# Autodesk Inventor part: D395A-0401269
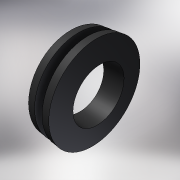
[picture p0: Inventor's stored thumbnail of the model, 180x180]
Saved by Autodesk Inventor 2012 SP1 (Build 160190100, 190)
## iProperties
Shininess: 69.0
Length Units: 11269
Angle Units: 11279
Time Units: 11290
Mass Units: 11283
Length Display Precision: 3
Angle Display Precision: 2
Created: 2002-06
Part Number: D395A-0401269
Material: Rubber
Document SubType Name: Modeling
Designer: LAlexey
Density: 0.93 g/cm^3
Mass: 3.61777 g
Surface Area: 34.5575 cm^2
Volume: 3.89008 cm^3
Density: 1.06
Volumn: 3.8900771033075623
Area: 34.55751918948772
PropertySet Name: Model Information
Control State: 0
Master: False
Checked Out: True
Checked Out Date: 2008-10-15
Last Check In Date: 2008-10-15
Author: LAlexey
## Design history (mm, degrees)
body "Solid1"
revolve "Revolution1" stored, may be unused: angle "d6" = 90 deg
sketch "Sketch1"
  geometry: L1 (0.27, 33.081)-(0.27, 40.581); L2 (0.27, 40.581)-(2.77, 40.581); L3 (2.77, 40.581)-(2.77, 36.081); L4 (2.77, 36.081)-(5.77, 36.081); L5 (5.77, 36.081)-(5.77, 40.581); L6 (5.77, 40.581)-(8.27, 40.581); L7 (8.27, 40.581)-(8.27, 33.081); L8 (8.27, 33.081)-(0.27, 33.081); L9 (6.357, 23.081)-(8.857, 23.081)
  constraints: 18 end point, 6 parallel, 2 equal length, 1 collinear, 1 perpendicular, 1 vertical
  dimensions: "d0" = 3 distance between parallel lines of L5 L3; "d1" = 10 distance between parallel lines of L9 L8; "d2" = 13 distance between parallel lines of L9 L4; "d3" = 0 distance between parallel lines of L6 L2; "d4" = 8 distance between parallel lines of L7 L1; "d5" = 17.5 distance between parallel lines of L9 L6
